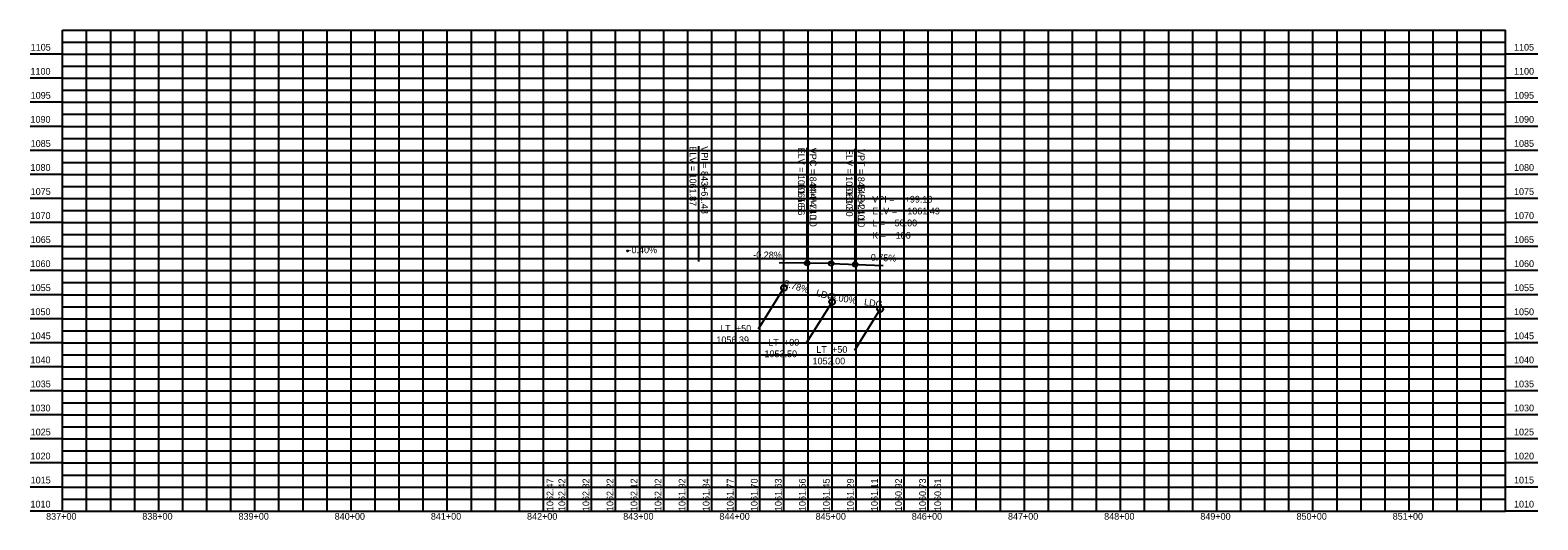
# Model space of a CAD drawing. Extents: x 234 to 2797, y 1001 to 3899.
# Drawn here: x 234 to 1802, y 1001 to 1510 of the extents above; entities that cross this region are included whole.
import ezdxf

# ---------------------------------------------------------------- set-up
doc = ezdxf.new("R2010")
doc.units = 0
for name, color, linetype in [('_CIVIL_CONSTRUCTION', 7, 'Continuous'), ('Alignment', 7, 'Continuous'), ('brgDimensionLines', 7, 'Continuous'), ('brgPreStructureNew', 7, 'Continuous'), ('Default', 7, 'Continuous'), ('Drain_Struc_Pr_CB_Std_048in_$Adhoc', 7, 'Continuous')]:
    doc.layers.add(name, color=color, linetype=linetype)

msp = doc.modelspace()

# ---------------------------------------------------------------- linework, layer by layer
at = {"layer": '_CIVIL_CONSTRUCTION'}
for p, q in [((929.5, 1269.4), (929.5, 1389.4)), ((929.5, 1269.4), (929.5, 1389.4)), ((1042.1, 1267.8), (1042.1, 1387.8)), ((1042.1, 1267.8), (1042.1, 1387.8)), ((1092.1, 1266.5), (1092.1, 1386.5)), ((1092.1, 1266.5), (1092.1, 1386.5)), ((1067.1, 1267.4), (1013.1, 1268.2)), ((1042.1, 1267.8), (1042.1, 1267.8)), ((1067.1, 1267.4), (1067.1, 1267.4)), ((1067.1, 1267.4), (1121.1, 1265.4)), ((1092.1, 1266.5), (1092.1, 1266.5)), ((1018, 1242), (991.2, 1199)), ((1068, 1227.5), (1041.2, 1184.6)), ((1118, 1220), (1091.2, 1177.1))]:
    msp.add_line(p, q, dxfattribs=at)
for centre, radius in [((1042.1, 1267.8), 2.43), ((1067.1, 1267.4), 2.43), ((1092.1, 1266.5), 2.43), ((1018, 1242), 3), ((1068, 1227.5), 3), ((1118, 1220), 3)]:
    msp.add_circle(centre, radius, dxfattribs=at)
at = {"layer": 'Alignment'}
msp.add_circle((855.5, 1280.5), 0.5, dxfattribs=at)
at = {"layer": 'brgDimensionLines'}
for p, q in [((268, 1010), (268, 1510)), ((368, 1010), (368, 1510)), ((468, 1010), (468, 1510)), ((568, 1010), (568, 1510)), ((668, 1010), (668, 1510)), ((768, 1010), (768, 1510)), ((868, 1010), (868, 1510)), ((968, 1010), (968, 1510)), ((1068, 1010), (1068, 1510)), ((1168, 1010), (1168, 1510)), ((1268, 1010), (1268, 1510)), ((1368, 1010), (1368, 1510)), ((1468, 1010), (1468, 1510)), ((1568, 1010), (1568, 1510)), ((1668, 1010), (1668, 1510)), ((268, 1485), (234.3, 1485)), ((268, 1485), (1768, 1485)), ((1801.8, 1485), (1768, 1485)), ((268, 1460), (234.3, 1460)), ((268, 1460), (1768, 1460)), ((1801.8, 1460), (1768, 1460)), ((268, 1435), (234.3, 1435)), ((268, 1435), (1768, 1435)), ((1801.8, 1435), (1768, 1435)), ((268, 1410), (234.3, 1410)), ((268, 1410), (1768, 1410)), ((1801.8, 1410), (1768, 1410)), ((268, 1385), (234.3, 1385)), ((268, 1385), (1768, 1385)), ((1801.8, 1385), (1768, 1385)), ((268, 1360), (234.3, 1360)), ((268, 1360), (1768, 1360)), ((1801.8, 1360), (1768, 1360)), ((268, 1335), (234.3, 1335)), ((268, 1335), (1768, 1335)), ((1801.8, 1335), (1768, 1335)), ((268, 1310), (234.3, 1310)), ((268, 1310), (1768, 1310)), ((1801.8, 1310), (1768, 1310)), ((268, 1285), (234.3, 1285)), ((268, 1285), (1768, 1285)), ((1801.8, 1285), (1768, 1285)), ((268, 1260), (234.3, 1260)), ((268, 1260), (1768, 1260)), ((1801.8, 1260), (1768, 1260)), ((268, 1235), (234.3, 1235)), ((268, 1235), (1768, 1235)), ((1801.8, 1235), (1768, 1235)), ((268, 1210), (234.3, 1210)), ((268, 1210), (1768, 1210)), ((1801.8, 1210), (1768, 1210)), ((268, 1185), (234.3, 1185)), ((268, 1185), (1768, 1185)), ((1801.8, 1185), (1768, 1185)), ((268, 1160), (234.3, 1160)), ((268, 1160), (1768, 1160)), ((1801.8, 1160), (1768, 1160)), ((268, 1135), (234.3, 1135)), ((268, 1135), (1768, 1135)), ((1801.8, 1135), (1768, 1135)), ((268, 1110), (234.3, 1110)), ((268, 1110), (1768, 1110)), ((1801.8, 1110), (1768, 1110)), ((268, 1085), (234.3, 1085)), ((268, 1085), (1768, 1085)), ((1801.8, 1085), (1768, 1085)), ((268, 1060), (234.3, 1060)), ((268, 1060), (1768, 1060)), ((1801.8, 1060), (1768, 1060)), ((268, 1035), (234.3, 1035)), ((268, 1035), (1768, 1035)), ((1801.8, 1035), (1768, 1035)), ((268, 1010), (234.3, 1010)), ((1801.8, 1010), (1768, 1010))]:
    msp.add_line(p, q, dxfattribs=at)
at = {"layer": 'brgPreStructureNew'}
for p, q in [((268, 1510), (1768, 1510)), ((268, 1010), (268, 1510)), ((1768, 1010), (1768, 1510)), ((268, 1010), (1768, 1010))]:
    msp.add_line(p, q, dxfattribs=at)
at = {"layer": 'Drain_Struc_Pr_CB_Std_048in_$Adhoc'}
for p, q in [((293, 1010), (293, 1510)), ((318, 1010), (318, 1510)), ((343, 1010), (343, 1510)), ((393, 1010), (393, 1510)), ((418, 1010), (418, 1510)), ((443, 1010), (443, 1510)), ((493, 1010), (493, 1510)), ((518, 1010), (518, 1510)), ((543, 1010), (543, 1510)), ((593, 1010), (593, 1510)), ((618, 1010), (618, 1510)), ((643, 1010), (643, 1510)), ((693, 1010), (693, 1510)), ((718, 1010), (718, 1510)), ((743, 1010), (743, 1510)), ((793, 1010), (793, 1510)), ((818, 1010), (818, 1510)), ((843, 1010), (843, 1510)), ((893, 1010), (893, 1510)), ((918, 1010), (918, 1510)), ((943, 1010), (943, 1510)), ((993, 1010), (993, 1510)), ((1018, 1010), (1018, 1510)), ((1043, 1010), (1043, 1510)), ((1093, 1010), (1093, 1510)), ((1118, 1010), (1118, 1510)), ((1143, 1010), (1143, 1510)), ((1193, 1010), (1193, 1510)), ((1218, 1010), (1218, 1510)), ((1243, 1010), (1243, 1510)), ((1293, 1010), (1293, 1510)), ((1318, 1010), (1318, 1510)), ((1343, 1010), (1343, 1510)), ((1393, 1010), (1393, 1510)), ((1418, 1010), (1418, 1510)), ((1443, 1010), (1443, 1510)), ((1493, 1010), (1493, 1510)), ((1518, 1010), (1518, 1510)), ((1543, 1010), (1543, 1510)), ((1593, 1010), (1593, 1510)), ((1618, 1010), (1618, 1510)), ((1643, 1010), (1643, 1510)), ((1693, 1010), (1693, 1510)), ((1718, 1010), (1718, 1510)), ((1743, 1010), (1743, 1510)), ((268, 1497.5), (1768, 1497.5)), ((268, 1472.5), (1768, 1472.5)), ((268, 1447.5), (1768, 1447.5)), ((268, 1422.5), (1768, 1422.5)), ((268, 1397.5), (1768, 1397.5)), ((268, 1372.5), (1768, 1372.5)), ((268, 1347.5), (1768, 1347.5)), ((268, 1322.5), (1768, 1322.5)), ((268, 1297.5), (1768, 1297.5)), ((268, 1272.5), (1768, 1272.5)), ((268, 1247.5), (1768, 1247.5)), ((268, 1222.5), (1768, 1222.5)), ((268, 1197.5), (1768, 1197.5)), ((268, 1172.5), (1768, 1172.5)), ((268, 1147.5), (1768, 1147.5)), ((268, 1122.5), (1768, 1122.5)), ((268, 1097.5), (1768, 1097.5)), ((268, 1072.5), (1768, 1072.5)), ((268, 1047.5), (1768, 1047.5)), ((268, 1022.5), (1768, 1022.5))]:
    msp.add_line(p, q, dxfattribs=at)

# ---------------------------------------------------------------- texts
at = {"layer": '_CIVIL_CONSTRUCTION'}
for s, height, p in [('1105', 7.02, (234.8, 1488.7)), ('1105', 7, (1777, 1488.7)), ('1100', 7.02, (234.6, 1463.7)), ('1100', 7, (1777, 1463.7)), ('1095', 7.02, (234.8, 1438.7)), ('1095', 7, (1777, 1438.7)), ('1090', 7.02, (234.6, 1413.7)), ('1090', 7, (1777, 1413.7)), ('1085', 7.02, (234.8, 1388.7)), ('1085', 7, (1777, 1388.7)), ('1080', 7.02, (234.6, 1363.7)), ('1080', 7, (1777, 1363.7)), ('1075', 7.02, (234.8, 1338.7)), ('VPI = ', 7.02, (1109.7, 1330.7)), ('+99.10', 7.02, (1143.4, 1330.7)), ('1075', 7, (1777, 1338.7)), ('1070', 7.02, (234.6, 1313.7)), ('ELV = ', 7.02, (1109.7, 1318.4)), ('1061.49', 7.02, (1146.2, 1318.4)), ('1070', 7, (1777, 1313.7)), ('L = ', 7.02, (1109.7, 1306.1)), ('50.00', 7.02, (1133, 1306.1)), ('1065', 7.02, (234.8, 1288.7)), ('K = ', 7.02, (1109.7, 1293.2)), ('106', 7.02, (1134.1, 1293.2)), ('1065', 7, (1777, 1288.7)), ('1060', 7.02, (234.6, 1263.7)), ('-0.40%', 7, (856.4, 1278.1)), ('1060', 7, (1777, 1263.7)), ('1055', 7.02, (234.8, 1238.7)), ('1055', 7, (1777, 1238.7)), ('1050', 7.02, (234.6, 1213.7)), ('1050', 7, (1777, 1213.7)), ('1045', 7.02, (234.8, 1188.7)), ('1056.39', 7.02, (947.7, 1184.5)), ('LT ', 7.02, (951.6, 1196.4)), ('+50', 7.02, (968, 1196.4)), ('1045', 7, (1777, 1188.7)), ('1053.50', 7.02, (997.7, 1170)), ('LT ', 7.02, (1001.6, 1182)), ('+00', 7.02, (1018, 1182)), ('LT ', 7.02, (1051.6, 1174.5)), ('+50', 7.02, (1068, 1174.5)), ('1040', 7.02, (234.6, 1163.7)), ('1052.00', 7.02, (1047.7, 1162.5)), ('1040', 7, (1777, 1163.7)), ('1035', 7.02, (234.8, 1138.7)), ('1035', 7, (1777, 1138.7)), ('1030', 7.02, (234.6, 1113.7)), ('1030', 7, (1777, 1113.7)), ('1025', 7.02, (234.8, 1088.7)), ('1025', 7, (1777, 1088.7)), ('1020', 7.02, (234.6, 1063.7)), ('1020', 7, (1777, 1063.7)), ('1015', 7.02, (234.8, 1038.7)), ('1015', 7, (1777, 1038.7)), ('1010', 7.02, (234.6, 1013.7)), ('1010', 7, (1777, 1013.7)), ('837+00', 7, (250.9, 1001)), ('838+00', 7, (350.9, 1001)), ('839+00', 7, (450.9, 1001)), ('840+00', 7, (550.9, 1001)), ('841+00', 7, (650.9, 1001)), ('842+00', 7, (750.9, 1001)), ('843+00', 7, (850.9, 1001)), ('844+00', 7, (950.9, 1001)), ('845+00', 7, (1050.9, 1001)), ('846+00', 7, (1150.9, 1001)), ('847+00', 7, (1250.9, 1001)), ('848+00', 7, (1350.9, 1001)), ('849+00', 7, (1450.9, 1001)), ('850+00', 7, (1550.9, 1001)), ('851+00', 7, (1650.9, 1001))]:
    msp.add_text(s, height=height, dxfattribs=at).set_placement(p)
for s, height, rotation, p in [('ELV = 1061.87', 7.02, 270, (919.8, 1389.4)), ('ELV = 1061.87', 7, 270, (919.9, 1389.3)), ('VPI = 843+61.43', 7, 270, (932, 1389.3)), ('VPI = 843+61.43', 7.02, 270, (932.1, 1389.4)), ('ELV = 1061.56', 7, 270, (1032.5, 1387.8)), ('ELV = ', 7.02, 270, (1032.5, 1387.8)), ('VPC', 7.02, 270, (1044.8, 1387.8)), ('VPC = 844+74.10', 7, 270, (1044.8, 1387.6)), ('ELV = 1061.30', 7, 270, (1082.5, 1386.5)), ('ELV = ', 7.02, 270, (1082.5, 1386.5)), ('VPT = 845+24.10', 7.02, 270, (1094.8, 1386.5)), ('VPT', 7.02, 270, (1094.8, 1386.5)), (' = ', 7.02, 270, (1044.8, 1368)), (' = ', 7.02, 270, (1094.8, 1367.5)), ('1061.56', 7.02, 270, (1032.5, 1351.3)), ('844+74.10', 7.02, 270, (1044.8, 1350.3)), ('1061.30', 7.02, 270, (1082.5, 1350.1)), ('845+24.10', 7.02, 270, (1094.8, 1349.8)), ('-0.28%', 7.02, 359.196, (986, 1273)), ('-0.75%', 7.02, 357.8459, (1105, 1270.5)), ('-5.78%', 7.02, 343.8807, (1014.3, 1244.6)), (' LDG', 7.02, 343.8807, (1048.2, 1234.8)), ('-3.00%', 7.02, 351.4692, (1063.5, 1229.8)), (' LDG', 7.02, 351.4692, (1098.4, 1224.6))]:
    msp.add_text(s, height=height, rotation=rotation, dxfattribs=at).set_placement(p)
at = {"layer": 'Default'}
for s, p in [('1062.47', (778.2, 1010)), ('1062.42', (790.6, 1010)), ('1062.32', (815.6, 1010)), ('1062.22', (840.6, 1010)), ('1062.12', (865.6, 1010)), ('1062.02', (890.6, 1010)), ('1061.92', (915.6, 1010)), ('1061.84', (940.6, 1010)), ('1061.77', (965.6, 1010)), ('1061.70', (990.6, 1010)), ('1061.63', (1015.6, 1010)), ('1061.56', (1040.6, 1010)), ('1061.45', (1065.6, 1010)), ('1061.29', (1090.6, 1010)), ('1061.11', (1115.6, 1010)), ('1060.92', (1140.6, 1010)), ('1060.73', (1165.6, 1010)), ('1060.61', (1181.4, 1010))]:
    msp.add_text(s, height=7.02, rotation=90, dxfattribs=at).set_placement(p)

doc.saveas('drawing.dxf')
